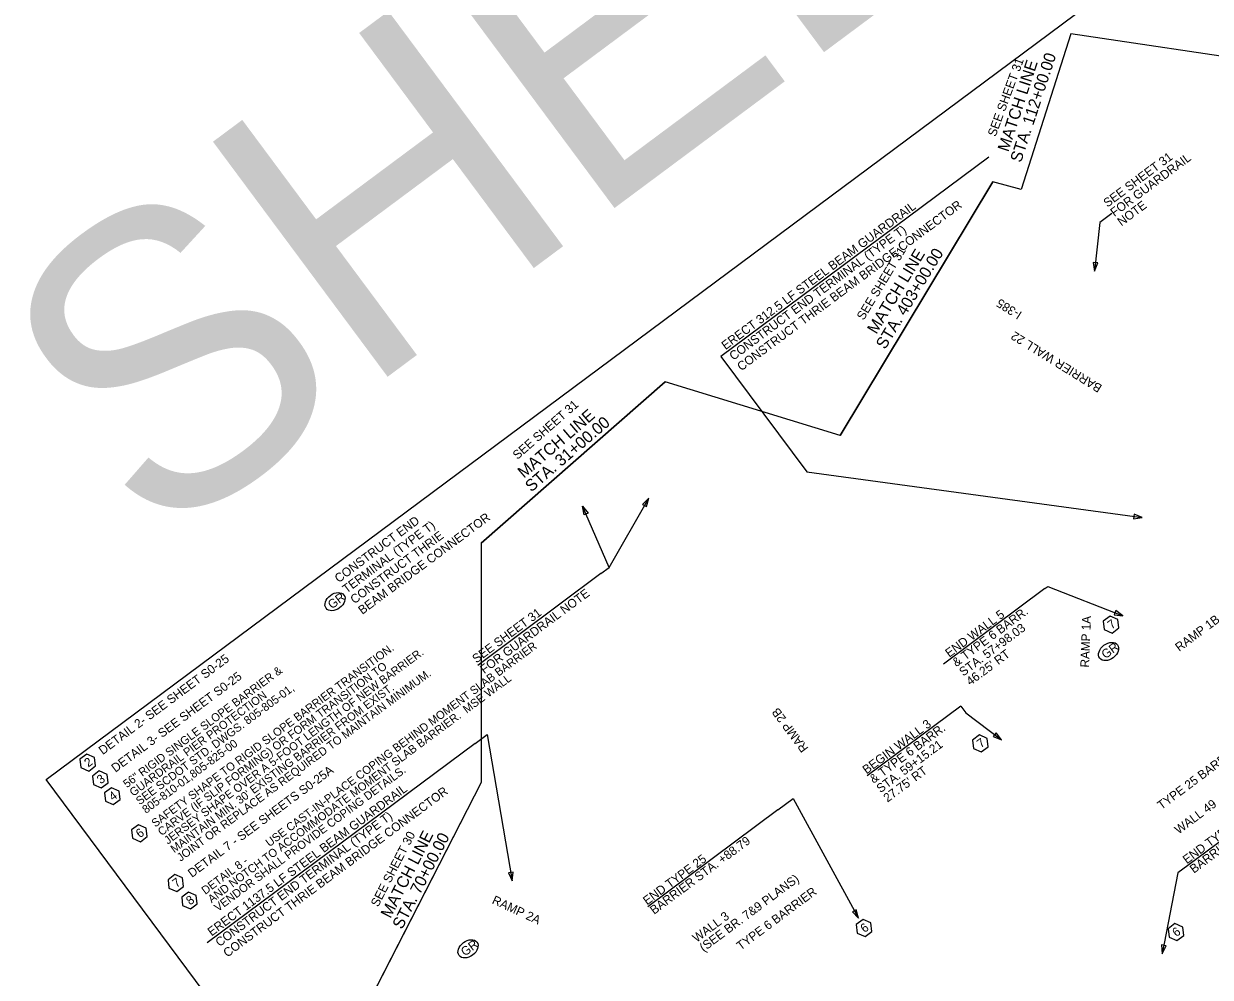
# Model space of a CAD drawing. Extents: x 1609621 to 1611756, y 1093008 to 1094970.
# Drawn here: x 1609826 to 1610636, y 1093658 to 1094309 of the extents above; entities that cross this region are included whole.
import ezdxf

# ---------------------------------------------------------------- set-up
doc = ezdxf.new("R2010")
doc.units = 0
for name, color, linetype in [('Level 2', 7, 'Continuous'), ('Plan_Clip', 7, 'Continuous'), ('RD_PD_GR_TX', 7, 'Continuous'), ('RD_SHT_MatchLine', 7, 'Continuous'), ('RD_SHT_Misc1', 7, 'Continuous'), ('RD_SHT_TX', 7, 'Continuous'), ('RD_TX_RoadID', 7, 'Continuous'), ('UC_AR_Telcom', 7, 'Continuous')]:
    doc.layers.add(name, color=color, linetype=linetype)

msp = doc.modelspace()

# ---------------------------------------------------------------- linework, layer by layer
at = {"layer": 'Level 2'}
msp.add_lwpolyline([(1609840.93, 1093792.96), (1611185.2, 1094792.24), (1611755.83, 1094024.6), (1610411.56, 1093025.32)], close=True, dxfattribs=at)
at = {"layer": 'Plan_Clip'}
msp.add_lwpolyline([(1610675.48, 1094282.16), (1610541.02, 1094302.11), (1610507.07, 1094195.84), (1610487.7, 1094201.18), (1610383.28, 1094027.81), (1610263.86, 1094064.61), (1610137.98, 1093954.45), (1610138.11, 1093790.92), (1610057.71, 1093634.14), (1610117.46, 1093588.58), (1610273.75, 1093378.33), (1610243.45, 1093357.42), (1610329.63, 1093200.98), (1610334.66, 1093203.95), (1610646.68, 1093232.42)], dxfattribs=at)
msp.add_lwpolyline([(1610675.48, 1094282.16), (1610541.02, 1094302.11), (1610507.07, 1094195.84), (1610487.7, 1094201.18), (1610383.28, 1094027.81), (1610263.86, 1094064.61), (1610137.98, 1093954.45), (1610138.11, 1093790.92), (1610057.71, 1093634.14), (1610117.46, 1093588.58), (1610273.75, 1093378.33), (1610243.45, 1093357.42), (1610329.63, 1093200.98), (1610334.66, 1093203.95), (1610646.68, 1093232.42)], dxfattribs=at)
at = {"layer": 'RD_PD_GR_TX'}
for p, q in [((1610484.94, 1094218.04), (1610301.89, 1094081.96)), ((1610225.59, 1093937.83), (1610207.37, 1093979.76)), ((1610219.86, 1093933.57), (1610135.65, 1093870.97)), ((1610133.83, 1093817.65), (1609950.79, 1093681.58))]:
    msp.add_line(p, q, dxfattribs=at)
for points in [[(1610568.92, 1094179.44), (1610560.68, 1094173.32), (1610557.09, 1094140.22)], [(1610301.89, 1094081.96), (1610360.49, 1094003.14), (1610589.66, 1093971.84)], [(1610219.86, 1093933.57), (1610225.59, 1093937.83), (1610252.52, 1093985.15)], [(1610133.83, 1093817.65), (1610142.06, 1093823.77), (1610159.3, 1093723.78)]]:
    msp.add_lwpolyline(points, dxfattribs=at)
for points in [[(1610556.17, 1094146.15), (1610557.09, 1094140.22), (1610559.26, 1094145.81)], [(1610251.01, 1093979.34), (1610252.52, 1093985.15), (1610248.31, 1093980.88)], [(1610208.32, 1093973.65), (1610207.37, 1093979.76), (1610211.08, 1093974.82)], [(1610583.7, 1093971.08), (1610589.66, 1093971.84), (1610584.12, 1093974.16)], [(1610156.78, 1093729.22), (1610159.3, 1093723.78), (1610159.84, 1093729.75)]]:
    msp.add_lwpolyline(points, close=True, dxfattribs=at)
msp.add_ellipse((1610038.18, 1093914.46), major_axis=(6.09, 4.53), ratio=0.697574, dxfattribs=at)
at = {"layer": 'RD_SHT_MatchLine'}
for p, q in [((1610541.02, 1094302.11), (1610507.07, 1094195.84)), ((1610383.28, 1094027.81), (1610487.7, 1094201.18)), ((1610137.98, 1093954.45), (1610263.86, 1094064.61)), ((1610138.11, 1093790.92), (1610057.71, 1093634.14))]:
    msp.add_line(p, q, dxfattribs=at)
at = {"layer": 'RD_SHT_TX'}
for p, q in [((1610523.21, 1093923.39), (1610453.9, 1093871.87)), ((1610465.83, 1093843.15), (1610401.75, 1093795.51)), ((1610709.63, 1093800.28), (1610620.75, 1093734.21)), ((1610340.84, 1093772.22), (1610251.96, 1093706.16))]:
    msp.add_line(p, q, dxfattribs=at)
for points in [[(1610523.21, 1093923.39), (1610525.12, 1093924.81), (1610576.47, 1093904.87)], [(1610465.83, 1093843.15), (1610469.2, 1093838.62), (1610493.46, 1093820.11)], [(1610340.84, 1093772.22), (1610351.31, 1093780.01), (1610395.76, 1093698.27)], [(1610620.75, 1093734.21), (1610614.08, 1093729.25), (1610603.34, 1093674.08)]]:
    msp.add_lwpolyline(points, dxfattribs=at)
for points in [[(1610573.04, 1093902.26), (1610567.71, 1093904.56), (1610563.04, 1093901.1), (1610563.72, 1093895.33), (1610569.05, 1093893.02), (1610573.71, 1093896.49)], [(1610570.5, 1093905.52), (1610576.47, 1093904.87), (1610571.63, 1093908.41)], [(1610483.73, 1093821.11), (1610478.4, 1093823.42), (1610473.74, 1093819.95), (1610474.41, 1093814.18), (1610479.74, 1093811.88), (1610484.4, 1093815.34)], [(1610487.91, 1093822.39), (1610493.46, 1093820.11), (1610489.79, 1093824.86)], [(1609873.89, 1093808.05), (1609868.56, 1093810.36), (1609863.89, 1093806.89), (1609864.57, 1093801.12), (1609869.9, 1093798.81), (1609874.56, 1093802.28)], [(1609882.45, 1093796.53), (1609877.12, 1093798.84), (1609872.46, 1093795.37), (1609873.13, 1093789.6), (1609878.46, 1093787.3), (1609883.12, 1093790.76)], [(1609890.7, 1093785.07), (1609885.37, 1093787.37), (1609880.7, 1093783.91), (1609881.37, 1093778.14), (1609886.71, 1093775.83), (1609891.37, 1093779.3)], [(1609909.24, 1093759.79), (1609903.91, 1093762.09), (1609899.24, 1093758.63), (1609899.91, 1093752.85), (1609905.25, 1093750.55), (1609909.91, 1093754.02)], [(1609934.08, 1093725.77), (1609928.75, 1093728.08), (1609924.09, 1093724.61), (1609924.76, 1093718.84), (1609930.09, 1093716.54), (1609934.75, 1093720)], [(1609943.43, 1093713.86), (1609938.1, 1093716.16), (1609933.43, 1093712.7), (1609934.1, 1093706.93), (1609939.44, 1093704.62), (1609944.1, 1093708.09)], [(1610391.63, 1093702.62), (1610395.76, 1093698.27), (1610394.36, 1093704.1)], [(1610404.28, 1093695.05), (1610398.95, 1093697.36), (1610394.29, 1093693.89), (1610394.96, 1093688.12), (1610400.29, 1093685.82), (1610404.95, 1093689.28)], [(1610617.35, 1093692.28), (1610612.02, 1093694.58), (1610607.36, 1093691.12), (1610608.03, 1093685.35), (1610613.36, 1093683.04), (1610618.03, 1093686.51)], [(1610602.92, 1093680.07), (1610603.34, 1093674.08), (1610605.97, 1093679.47)]]:
    msp.add_lwpolyline(points, close=True, dxfattribs=at)
at = {"layer": 'UC_AR_Telcom'}
for centre in [(1610566.72, 1093880.43), (1610129.05, 1093677.37)]:
    msp.add_ellipse(centre, major_axis=(6.09, 4.53), ratio=0.697574, dxfattribs=at)

# ---------------------------------------------------------------- texts
at = {"layer": 'RD_PD_GR_TX'}
for s, rotation, p in [('SEE SHEET 31 ', 36.62722, (1610565.94, 1094183.46)), ('FOR GUARDRAIL', 36.62722, (1610570.71, 1094177.04)), ('ERECT 312.5 LF STEEL BEAM GUARDRAIL', 36.62722, (1610305.01, 1094086.15)), ('CONSTRUCT THRIE BEAM BRIDGE CONNECTOR', 36.62722, (1610315.75, 1094071.71)), ('NOTE', 36.62722, (1610575.49, 1094170.62)), ('CONSTRUCT END TERMINAL (TYPE T)', 36.62722, (1610310.38, 1094078.93)), ('BEAM BRIDGE CONNECTOR', 36.62559, (1610056.82, 1093905.4)), ('CONSTRUCT END ', 36.62559, (1610040.71, 1093927.07)), ('TERMINAL (TYPE T)', 36.62559, (1610046.08, 1093919.85)), ('CONSTRUCT THRIE ', 36.62559, (1610051.45, 1093912.62)), ('GR', 36.62559, (1610036.06, 1093909.15)), ('FOR GUARDRAIL NOTE', 36.62559, (1610140.12, 1093864.95)), ('SEE SHEET 31', 36.62559, (1610134.76, 1093872.17)), ('ERECT 1137.5 LF STEEL BEAM GUARDRAIL', 36.62722, (1609953.9, 1093685.76)), ('CONSTRUCT THRIE BEAM BRIDGE CONNECTOR', 36.62722, (1609964.64, 1093671.32)), ('CONSTRUCT END TERMINAL (TYPE T)', 36.62722, (1609959.27, 1093678.54))]:
    msp.add_text(s, height=6, rotation=rotation, dxfattribs=at).set_placement(p)
at = {"layer": 'RD_SHT_MatchLine'}
for s, height, rotation, p in [('SEE SHEET 31', 6, 69.84075, (1610489.52, 1094231.57)), ('MATCH LINE', 8, 71.83966, (1610498.21, 1094221.16)), ('STA. 112+00.00', 8, 71.83966, (1610506.85, 1094213.83)), ('SEE SHEET 31', 6, 58.86367, (1610399.37, 1094106.24)), ('MATCH LINE', 8, 58.8124, (1610408.06, 1094096.63)), ('STA. 403+00.00', 8, 58.8124, (1610414.02, 1094086.23)), ('SEE SHEET 31', 6, 41.18742, (1610162.8, 1094011.18)), ('MATCH LINE', 8, 40.59074, (1610167.22, 1093998.39)), ('STA. 31+00.00', 8, 40.59074, (1610172.33, 1093988.96)), ('SEE SHEET 30', 6, 62.84804, (1610067.62, 1093705.57)), ('MATCH LINE', 8, 62.84804, (1610076.05, 1093697.7)), ('STA. 70+00.00', 8, 62.84804, (1610084, 1093690.22))]:
    msp.add_text(s, height=height, rotation=rotation, dxfattribs=at).set_placement(p)
at = {"layer": 'RD_SHT_Misc1'}
msp.add_text('SHEET 12-1', height=200, rotation=36.62559, dxfattribs=at).set_placement((1609913.35, 1093948.51))
at = {"layer": 'RD_SHT_TX'}
for s, height, rotation, p in [('BARRIER WALL 22', 6, 148.20635, (1610562.76, 1094061.95)), ('END WALL 5', 6, 36.62559, (1610457.89, 1093876.08)), ('& TYPE 6 BARR.', 6, 36.62559, (1610462.67, 1093869.66)), ('7', 6, 36.62559, (1610568.76, 1093895.34)), ('STA. 57+98.03', 6, 36.62559, (1610467.44, 1093863.24)), ('USE CAST-IN-PLACE COPING BEHIND MOMENT SLAB BARRIER', 5.6, 36.62559, (1609993.34, 1093746.74)), ('GR', 6, 36.62559, (1610564.6, 1093875.12)), ('DETAIL 2- SEE SHEET S0-25', 6, 36.62559, (1609879.5, 1093809.61)), ('SAFETY SHAPE TO RIGID SLOPE BARRIER TRANSITION. ', 5.6, 36.62559, (1609915.36, 1093760.12)), ('JERSEY SHAPE OVER A 5-FOOT LENGTH OF NEW BARRIER.', 5.6, 36.62559, (1609924.04, 1093748.43)), ("46.25' RT", 6, 36.62559, (1610472.21, 1093856.82)), ('56" RIGID SINGLE SLOPE BARRIER &', 5.6, 36.62559, (1609896.03, 1093787.01)), ('CARVE (IF SLIP FORMING) OR FORM TRANSITION TO ', 5.6, 36.62559, (1609919.7, 1093754.27)), ('DETAIL 3- SEE SHEET S0-25', 6, 36.62559, (1609888.16, 1093797.59)), ('JOINT OR REPLACE AS REQUIRED TO MAINTAIN MINIMUM.', 5.6, 36.62559, (1609932.73, 1093736.75)), ('AND NOTCH TO ACCOMMODATE MOMENT SLAB BARRIER.  MSE WALL ', 5.6, 36.62559, (1609953.89, 1093708.35)), ('GUARDRAIL PIER PROTECTION', 5.6, 36.62559, (1609900.37, 1093781.17)), ('SEE SCDOT STD. DWGS. 805-805-01,', 5.6, 36.62559, (1609904.71, 1093775.32)), ("MAINTAIN MIN. 30' EXISTING BARRIER FROM EXIST. ", 5.6, 36.62559, (1609928.39, 1093742.59)), ('BEGIN WALL 3', 6, 36.62559, (1610401.35, 1093796.45)), ('& TYPE 6 BARR.', 6, 36.62559, (1610406.12, 1093790.03)), ('805-810-01,805-825-00', 5.6, 36.62559, (1609909.06, 1093769.48)), ('7', 6, 36.62559, (1610479.46, 1093814.2)), ('STA. 59+15.21', 6, 36.62559, (1610410.89, 1093783.61)), ('TYPE 25 BARRIER', 6, 36.62559, (1610602.81, 1093772.12)), ('2', 6, 36.62559, (1609869.61, 1093801.14)), ('3', 6, 36.62559, (1609878.18, 1093789.62)), ('DETAIL 7 - SEE SHEETS S0-25A', 6, 36.62559, (1609940.44, 1093725.78)), ('VENDOR SHALL PROVIDE COPING DETAILS.', 5.6, 36.62559, (1609958.23, 1093702.51)), ("27.75' RT", 6, 36.62559, (1610415.67, 1093777.19)), ('4', 6, 36.62559, (1609886.42, 1093778.15)), ('BARRIER STA. +40.95', 6, 36.62559, (1610624.97, 1093728.63)), ('WALL 49', 6, 36.62559, (1610614.56, 1093755.39)), ('END TYPE 25 ', 6, 36.62559, (1610620.19, 1093735.05)), ('6', 6, 36.62559, (1609904.85, 1093752.79)), ('BARRIER STA. +88.79', 6, 36.62559, (1610256.18, 1093700.57)), ('END TYPE 25 ', 6, 36.62559, (1610251.4, 1093706.99)), ('DETAIL 8 - ', 5.6, 36.62559, (1609949.55, 1093714.19)), ('7', 6, 36.62559, (1609929.81, 1093718.86)), ('(SEE BR. 7&9 PLANS)', 6, 36.62559, (1610290.01, 1093675.05)), ('TYPE 6 BARRIER', 6, 36.62559, (1610315.3, 1093676.12)), ('8', 6, 36.62559, (1609939.15, 1093706.94)), ('WALL 3', 6, 36.62559, (1610285.23, 1093681.47)), ('6', 6, 36.62559, (1610399.89, 1093688.05)), ('6', 6, 36.62559, (1610612.97, 1093685.28)), ('GR', 6, 36.62559, (1610126.94, 1093672.06))]:
    msp.add_text(s, height=height, rotation=rotation, dxfattribs=at).set_placement(p)
at = {"layer": 'RD_TX_RoadID'}
for s, rotation, p in [('I-385', 147.53424, (1610508.01, 1094111.86)), ('RAMP 1A', 87.86457, (1610553.35, 1093869.4)), ('RAMP 1B', 36.62559, (1610614.99, 1093880.09)), ('RAMP 2B', 126.66494, (1610361.92, 1093814.35)), ('RAMP 2A', 335.20828, (1610144.95, 1093708.59))]:
    msp.add_text(s, height=6, rotation=rotation, dxfattribs=at).set_placement(p)

doc.saveas('drawing.dxf')
